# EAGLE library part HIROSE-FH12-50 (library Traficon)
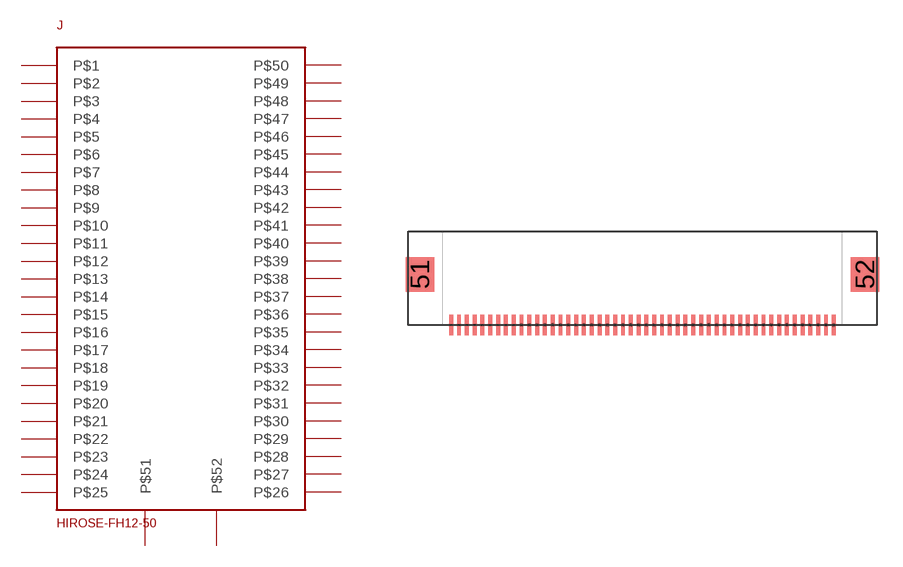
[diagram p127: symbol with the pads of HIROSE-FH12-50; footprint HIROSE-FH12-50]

Designator prefix J

## HIROSE-FH12-50  [HIROSE-FH12-50]
1  P$1
2  P$2
3  P$3
4  P$4
5  P$5
6  P$6
7  P$7
8  P$8
9  P$9
10  P$10
11  P$11
12  P$12
13  P$13
14  P$14
15  P$15
16  P$16
17  P$17
18  P$18
19  P$19
20  P$20
21  P$21
22  P$22
23  P$23
24  P$24
25  P$25
26  P$26
27  P$27
28  P$28
29  P$29
30  P$30
31  P$31
32  P$32
33  P$33
34  P$34
35  P$35
36  P$36
37  P$37
38  P$38
39  P$39
40  P$40
41  P$41
42  P$42
43  P$43
44  P$44
45  P$45
46  P$46
47  P$47
48  P$48
49  P$49
50  P$50
51  P$52
52  P$51

## Footprint HIROSE-FH12-50 (pad centres in mm)
smd 0.25 x 1.3: 1 -12.25,0; 2 -11.75,0; 3 -11.25,0; 4 -10.75,0; 5 -10.25,0; 6 -9.75,0; 7 -9.25,0; 8 -8.75,0; 9 -8.25,0; 10 -7.75,0; 11 -7.25,0; 12 -6.75,0; 13 -6.25,0; 14 -5.75,0; 15 -5.25,0; 16 -4.75,0; 17 -4.25,0; 18 -3.75,0; 19 -3.25,0; 20 -2.75,0; 21 -2.25,0; 22 -1.75,0; 23 -1.25,0; 24 -0.75,0; 25 -0.25,0; 26 0.25,0; 27 0.75,0; 28 1.25,0; 29 1.75,0; 30 2.25,0; 31 2.75,0; 32 3.25,0; 33 3.75,0; 34 4.25,0; 35 4.75,0; 36 5.25,0; 37 5.75,0; 38 6.25,0; 39 6.75,0; 40 7.25,0; 41 7.75,0; 42 8.25,0; 43 8.75,0; 44 9.25,0; 45 9.75,0; 46 10.25,0; 47 10.75,0; 48 11.25,0; 49 11.75,0; 50 12.25,0
smd 1.8 x 2.2: 51 -14.25,3.25; 52 14.25,3.25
